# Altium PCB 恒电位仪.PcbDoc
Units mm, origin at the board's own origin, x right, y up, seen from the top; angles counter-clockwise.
Board outline 89.66 x 76.33 mm, 2 copper layers (Top Layer, Bottom Layer); 52 components, 39 nets, 177 pads, 10 vias.
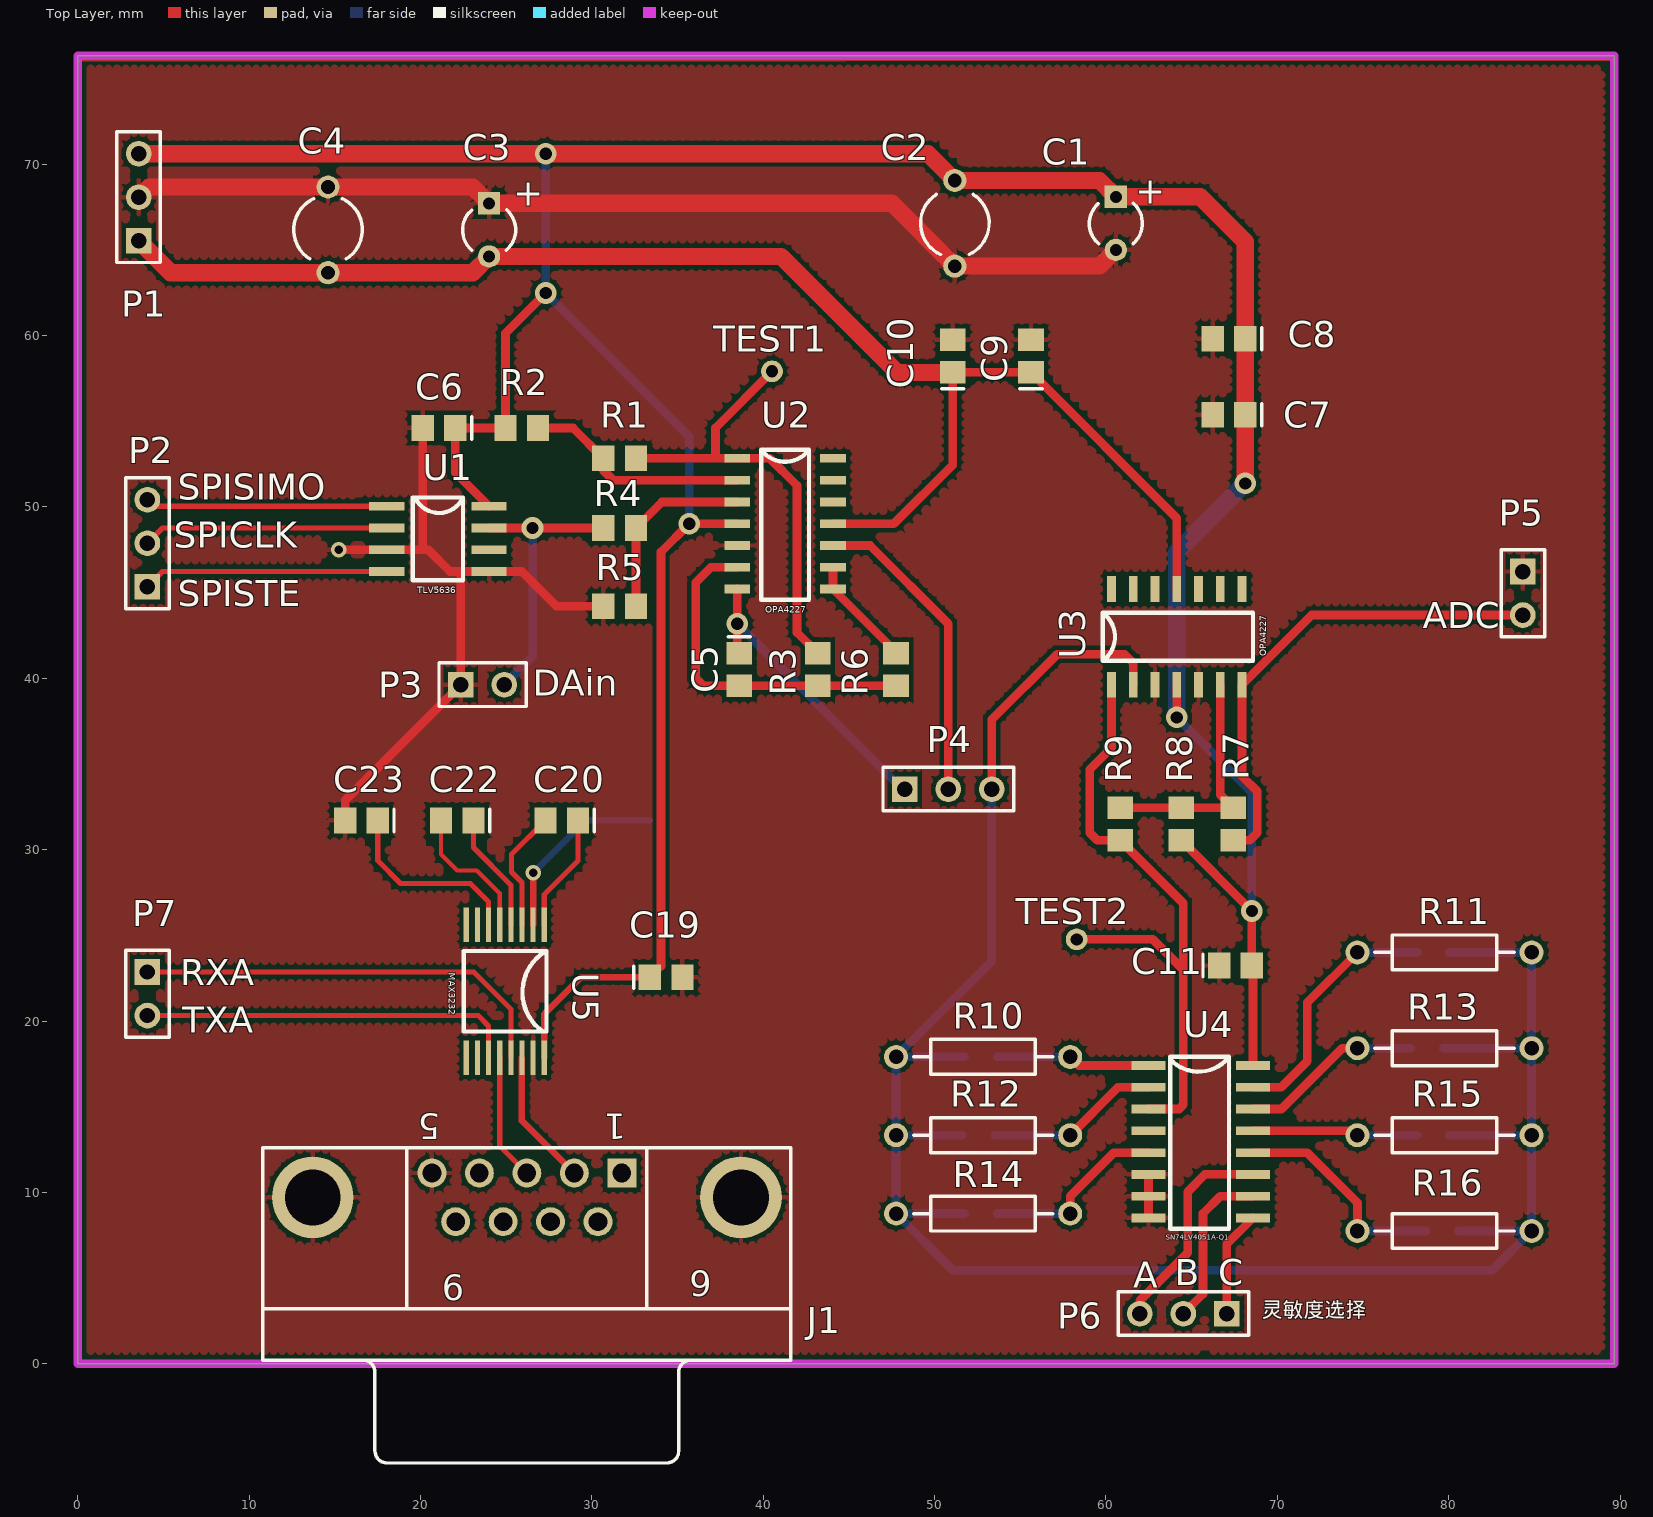
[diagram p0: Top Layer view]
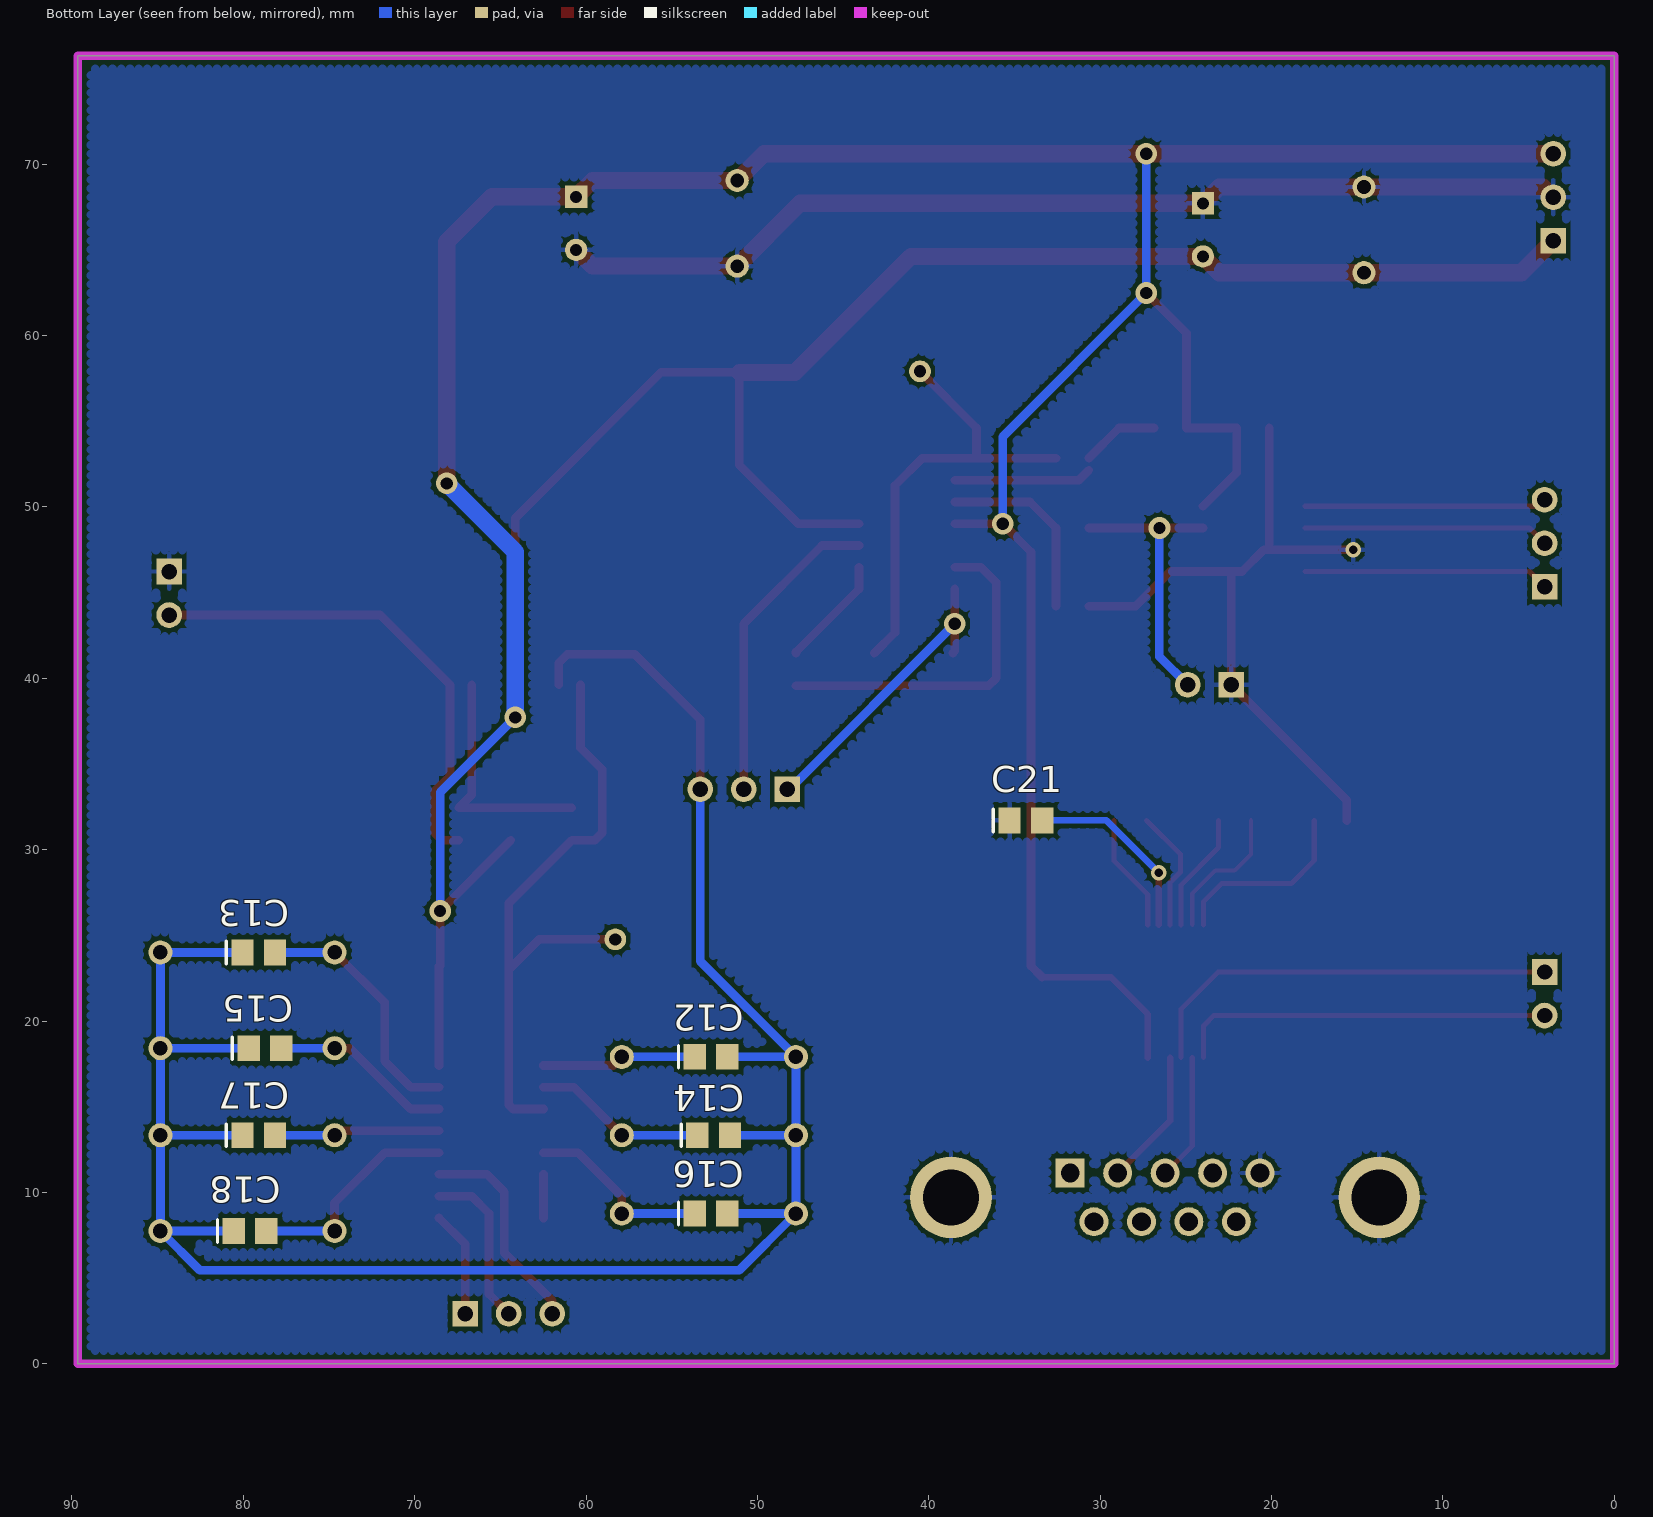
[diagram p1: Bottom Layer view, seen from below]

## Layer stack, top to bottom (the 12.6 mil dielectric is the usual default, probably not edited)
Top Layer: signal copper 0.0356
Dielectric: dielectric 0.32, FR-4, Dk 4.8
Bottom Layer: signal copper 0.0356

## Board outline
0,0 89.662,0 89.662,76.327 0,76.327

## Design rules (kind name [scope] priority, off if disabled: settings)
Clearance [All] p1: gap=0.254
ComponentClearance [All] p1 off: gap=0.254 collisioncheckmode=3 verticalgap=0.254
HoleSize [All] p1: absolutevalues=TRUE maxlimit=5.08 minlimit=0.025 maxpercent=80.000 minpercent=20.000
PolygonConnect [All] p1: connectstyle=Relief reliefconductorwidth=0.254 reliefentries=4 polygonreliefangle="90 Angle"
RoutingVias [All] p1: holewidth=0.511 width=1.27 viastyle="Through Hole" minholewidth=0.211 minwidth=0.7 maxholewidth=1.012 maxwidth=1.27
SolderMaskExpansion [All] p1: expansion=0.102
TestPointUsage [All] p1: valid=0 allowmultiple=FALSE
Testpoint [All] p1: side=15 testpointundercomponent=TRUE minsize=1.016 maxsize=2.54 preferedsize=1.524 minholesize=0 maxholesize=1.016 preferedholesize=0.813 testpointgrid=0.025 style=1023 order=0-112345678
Width GND [InNet('GND')] p1: maxlimit=1.2 minlimit=0.254 preferedwidth=0.508
Width -5V [InNet('-5V')] p2: maxlimit=1.2 minlimit=0.254 preferedwidth=0.508
Width +5V [InNet('+5V')] p3: maxlimit=1.262 minlimit=0.254 preferedwidth=0.508
Width [All] p4: maxlimit=0.762 minlimit=0.254 preferedwidth=0.254
17 further rules are at their usual default settings.

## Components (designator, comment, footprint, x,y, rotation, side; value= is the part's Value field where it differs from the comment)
C1 "Cap Pol1" R38 60.579,66.548 r0 top
C2 "Cap" CAPR5-4X5 51.181,66.548 r270 top
C3 "Cap Pol1" R38 24.003,66.167 r0 top
C4 "Cap" CAPR5-4X5 14.605,66.167 r90 top
C5 "Cap" C0805 38.608,40.513 r270 top
C6 "Cap" C0805 21.082,54.61 r180 top
C7 "Cap" C0805 67.183,55.372 r180 top
C8 "Cap" C0805 67.183,59.817 r180 top
C9 "Cap" C0805 55.626,58.801 r90 top
C10 "Cap" C0805 51.054,58.801 r90 top
C11 "Cap" C0805 67.564,23.241 r0 top
C12 "Cap" C0805 52.705,17.907 r180 bottom
C13 "Cap" C0805 79.099,24.003 r180 bottom
C14 "Cap" C0805 52.556,13.335 r180 bottom
C15 "Cap" C0805 78.74,18.415 r180 bottom
C16 "Cap" C0805 52.705,8.763 r180 bottom
C17 "Cap" C0805 79.099,13.335 r180 bottom
C18 "Cap" C0805 79.607,7.747 r180 bottom
C19 "Cap" C0805 34.335,22.561 r0 top
C20 "Cap" C0805 28.239,31.705 r180 top
C21 "Cap" C0805 34.335,31.705 r180 bottom
C22 "Cap" C0805 22.143,31.705 r180 top
C23 "Cap" C0805 16.555,31.705 r180 top
J1 "D Connector 9" DSUB1.385-2H9 26.207,0.209 r180 top
P1 "Header 3" HDR1X3 3.556,65.532 r90 top
P2 "Header 3" HDR1X3 4.064,45.339 r90 top
P3 "Header 2" HDR1X2 22.352,39.624 r0 top
P4 "Header 3" HDR1X3 48.26,33.528 r0 top
P5 "Header 2" HDR1X2 84.328,46.228 r270 top
P6 "Header 3" HDR1X3 67.056,2.921 r180 top
P7 "Header 2" HDR1X2 4.064,22.86 r270 top
R1 "Res2" 6-0805 31.623,52.832 r0 top
R2 "Res2" 6-0805 25.908,54.61 r0 top
R3 "Res2" 6-0805 43.18,40.513 r90 top
R4 "Res2" 6-0805 31.623,48.768 r0 top
R5 "Res2" 6-0805 31.623,44.196 r0 top
R6 "Res2" 6-0805 47.752,40.513 r270 top
R7 "Res2" 6-0805 67.437,31.496 r270 top
R8 "Res2" 6-0805 64.389,31.496 r90 top
R9 "Res2" 6-0805 60.833,31.496 r90 top
R10 "Res2" AXIAL-0.4 52.832,17.907 r180 top
R11 "Res2" AXIAL-0.4 79.756,24.003 r180 top
R12 "Res2" AXIAL-0.4 52.832,13.335 r180 top
R13 "Res2" AXIAL-0.4 79.756,18.415 r180 top
R14 "Res2" AXIAL-0.4 52.832,8.763 r180 top
R15 "Res2" AXIAL-0.4 79.756,13.335 r180 top
R16 "Res2" AXIAL-0.4 79.756,7.747 r180 top
U1 "TLV5636" TLV5636 18.034,50.038 r0 top
U2 "OPA4227" OPA4227 38.481,52.832 r0 top
U3 "OPA4227" OPA4227 60.325,39.624 r90 top
U4 "SN74LV4051A-Q1" SN74LV4051A-Q1 62.484,17.399 r0 top
U5 "MAX3232" MAX3232 27.223,25.609 r270 top

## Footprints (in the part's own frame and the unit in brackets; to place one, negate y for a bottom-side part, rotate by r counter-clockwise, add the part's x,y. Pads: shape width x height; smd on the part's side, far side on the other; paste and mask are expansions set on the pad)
6-0805 [mm] "Chip Resistor; Body 2.0 x 1.3 mm (LxW typ)"
  rect 1.3x1.5 smd: 1(-0.95,0) 2(0.95,0)
AXIAL-0.4 [mm] "Resistor; 2 Leads"
  round 1.4 hole 0.85: 1(-5.08,0) 2(5.08,0)
  silkscreen extent -4.06,-1.02 4.06,1.02
C0805 [mm] "Chip Capacitor; Body 2.0 x 1.2 mm (LxW typ)"
  rect 1.3x1.5 smd: 1(-0.95,0) 2(0.95,0)
  silkscreen extent -1.9,-0.65 -1.9,0.65
CAPR5-4X5 [mm] "Capacitor; 2 Leads"
  round 1.35 hole 0.8: 1(-2.5,0) 2(2.5,0)
  silkscreen extent -1.69,-2 1.82,2
DSUB1.385-2H9 [mm] "Connector; D Subminiature; 9 Position; Right Angle; Pitch 1.385 mm"
  rect 1.69x1.69 hole 1.09: 1(-5.54,-10.92)
  round 1.69 hole 1.09: 2(-2.77,-10.92) 3(0,-10.92) 4(2.77,-10.92) 5(5.54,-10.92) 6(-4.155,-8.08) 7(-1.385,-8.08) 8(1.385,-8.08) 9(4.155,-8.08)
  round 4.76 hole 3.26: 10(-12.495,-9.5) 11(12.495,-9.5)
  silkscreen extent -15.4,-12.4 15.4,6
HDR1X2 [mm] "Connector; Header; 2 Position"
  rect 1.5x1.5 hole 0.9: 1(0,0)
  round 1.5 hole 0.9: 2(2.54,0)
  silkscreen extent -1.27,-1.27 3.81,1.27
HDR1X3 [mm] "Connector; Header; 3 Position"
  rect 1.5x1.5 hole 0.9: 1(0,0)
  round 1.5 hole 0.9: 2(2.54,0) 3(5.08,0)
  silkscreen extent -1.27,-1.27 6.35,1.27
MAX3232 [mm]
  rect 2x0.3 smd: 1(0,0) 2(0,-0.65) 3(0,-1.3) 4(0,-1.95) 5(0,-2.6) 6(0,-3.25) 7(0,-3.9) 8(0,-4.55) 9(7.747,-4.55) 10(7.747,-3.9) 11(7.747,-3.25) 12(7.747,-2.6) 13(7.747,-1.95) 14(7.747,-1.3) 15(7.747,-0.65) 16(7.747,0)
  silkscreen extent 1.52,-4.7 6.22,0.13
OPA4227 [mm]
  rect 1.5x0.51 smd: 1(0,0) 2(0,-1.27) 3(0,-2.54) 4(0,-3.81) 5(0,-5.08) 6(0,-6.35) 7(0,-7.62) 8(5.588,-7.62) 9(5.588,-6.35) 10(5.588,-5.08) 11(5.588,-3.81) 12(5.588,-2.54) 13(5.588,-1.27) 14(5.588,0)
  silkscreen extent 1.4,-8.25 4.19,0.51
R38 [mm] "Crystal, Thru-Hole; 2 Leads; Body 3.1 x 8.2 mm (Dia.xH)"
  rect 1.3x1.3 hole 0.7: 1(0,1.55)
  round 1.3 hole 0.7: 2(0,-1.55)
  silkscreen extent -1.55,-1.19 1.55,1.17
SN74LV4051A-Q1 [mm]
  rect 2x0.51 smd: 1(0,0) 2(0,-1.27) 3(0,-2.54) 4(0,-3.81) 5(0,-5.08) 6(0,-6.35) 7(0,-7.62) 8(0,-8.89) 9(6.096,-8.89) 10(6.096,-7.62) 11(6.096,-6.35) 12(6.096,-5.08) 13(6.096,-3.81) 14(6.096,-2.54) 15(6.096,-1.27) 16(6.096,0)
  silkscreen extent 1.26,-9.53 4.7,0.51
TLV5636 [mm]
  rect 2.05x0.51 smd: 1(0,0) 2(0,-1.27) 3(0,-2.54) 4(0,-3.81) 5(5.969,-3.81) 6(5.969,-2.54) 7(5.969,-1.27) 8(5.969,0)
  silkscreen extent 1.52,-4.32 4.44,0.51

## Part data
C1 C3: "Polarized Capacitor (Radial)"
C2 C4 C5 C6 C7 C8 C9 C10 C11 C12 C13 C14 C15 C16 C17 C18 C19 C20 C21 C22 C23: "Capacitor"
J1: "Receptacle Assembly, 9 Position, Right Angle"
P1 P2 P4 P6: "Header, 3-Pin"
P3 P5 P7: "Header, 2-Pin"
R1 R2 R3 R4 R5 R6 R7 R8 R9 R10 R11 R12 R13 R14 R15 R16: "Resistor"

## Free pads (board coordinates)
  round 1.27 hole 0.711: 1(40.513,57.912) 2(58.293,24.765)

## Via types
v1: diameter 1.27, hole 0.711, Top Layer to Bottom Layer, 8 vias
v2: diameter 0.9, hole 0.5, Top Layer to Bottom Layer, 2 vias

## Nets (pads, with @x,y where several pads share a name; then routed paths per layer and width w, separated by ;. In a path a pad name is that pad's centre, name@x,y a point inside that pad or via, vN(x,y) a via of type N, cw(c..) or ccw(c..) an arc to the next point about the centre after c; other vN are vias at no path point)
+5: 
+5V: C1.1 C2.1 C6.1 C7.1 C8.1 C11.2 C19.1 P1.3 R2.1 R8.1 U1.8 U2.4 U3.4 U4.16 U5.16 | length 208.2
  Top Layer w0.381: U5.16 27.223,20.402 29.382,22.561 C19.1
  Top Layer w0.508: U1.8 22.032,52.009 C6.1 R2.1 24.958,60.137 v1(27.305,62.484) ; C19.1 34.036,23.212 34.036,47.371 v1(35.687,49.022) U2.4 ; 39.116,70.485 39.116,70.612 ; v1(64.135,37.719) U3.4 ; R8.1 v1(68.514,26.421) C11.2 68.58,23.175 U4.16
  Top Layer w1: P1.3 49.617,70.612 C2.1 59.629,69.048 C1.1 65.506,68.098 68.133,65.471 v1(68.133,51.374)
  Bottom Layer w0.508: v1(27.305,70.612) v1(27.305,62.484) 35.687,54.102 v1(35.687,49.022) ; v1(64.135,37.719) 68.514,33.34 v1(68.514,26.421)
  Bottom Layer w1: v1(64.135,37.719) 64.135,47.376 v1(68.133,51.374)
-5V: C3.2 C4.1 C9.1 C10.1 P1.1 U2.11 U3.11 | length 86
  Top Layer w0.508: U2.11 47.625,49.022 51.054,52.451 C10.1 C9.1 64.135,49.342 U3.11
  Top Layer w1: P1.1 5.421,63.667 23.053,63.667 C3.2 41.047,64.617 47.813,57.851 C10.1
A: P6.3 U4.11 | length 12.5
  Top Layer w0.508: P6.3 61.976,3.683 64.77,6.477 64.77,10.033 65.786,11.049 U4.11
B: P6.2 U4.10 | length 9.7
  Top Layer w0.508: P6.2 65.659,4.064 65.659,8.763 66.675,9.779 U4.10
C: P6.1 U4.9 | length 6.2
  Top Layer w0.508: P6.1 67.056,6.985 U4.9
GND: C1.2 C2.2 C3.1 C4.2 C6.2 C7.2 C8.2 C9.2 C10.2 C11.1 C19.2 C21.1 C23.2 J1.5 J1.10 J1.11 P1.2 P3.1 P5.1 R5.1 U1.3 U1.5 U2.5 U3.3 U3.5 U4.6 U4.7 U4.8 U5.15 | length 103.4
  Top Layer w0.508: v2(15.24,47.498) 20.447,47.498 21.717,46.228 25.908,46.228 27.94,44.196 R5.1 ; C23.2 15.605,32.877 P3.1 22.352,46.228 ; 20.066,47.498 20.132,47.564 C6.2 ; U4.8 U4.6
  Top Layer w1: P1.2 4.151,68.667 23.053,68.667 C3.1 47.512,67.717 C2.2 59.629,64.048 C1.2
NetC5_1: C5.1 P4.1 U2.7 | length 17.6
  Top Layer w0.508: U2.7 38.481,41.59 C5.1
  Bottom Layer w0.508: v1(38.481,43.18) 48.133,33.528 P4.1
NetC5_2: C5.2 R3.1 R6.2 U2.6 | length 20.2
  Top Layer w0.508: U2.6 36.957,46.482 36.068,45.593 36.068,40.005 36.51,39.563 C5.2 R3.1 R6.2
NetC12_1: C12.1 R10.1 U4.1 | length 9
  Top Layer w0.508: R10.1 58.42,17.399 U4.1
  Bottom Layer w0.508: C12.1 R10.1
NetC12_2: C12.2 C13.1 C14.2 C15.1 C16.2 C17.1 C18.1 P4.3 R10.2 R11.1 R12.2 R13.1 R14.2 R15.1 R16.1 U3.2 | length 129
  Top Layer w0.508: P4.3 53.34,37.592 57.15,41.402 61.087,41.402 61.595,40.894 U3.2
  Bottom Layer w0.508: R12.2 C14.2 ; C16.2 R14.2 ; C12.2 R10.2 ; P4.3 53.34,23.495 R10.2 ; C15.1 R13.1 ; C17.1 R15.1 ; C13.1 R11.1 R13.1 ; C18.1 R16.1 ; R14.2 R10.2 ; R14.2 51.054,5.461 82.55,5.461 R16.1 ; R16.1 R15.1 ; R15.1 R13.1
NetC13_2: C13.2 R11.2 U4.15 | length 14.8
  Top Layer w0.508: U4.15 70.231,16.129 71.755,17.653 71.755,21.082 R11.2
  Bottom Layer w0.508: R11.2 C13.2
NetC14_1: C14.1 R12.1 U4.2 | length 10.1
  Top Layer w0.508: R12.1 60.706,16.129 U4.2
  Bottom Layer w0.508: C14.1 R12.1
NetC15_2: C15.2 R13.2 U4.14 | length 10.7
  Top Layer w0.508: U4.14 70.231,14.859 73.787,18.415 R13.2
  Bottom Layer w0.508: R13.2 C15.2
NetC16_1: C16.1 R14.1 U4.5 | length 10.9
  Top Layer w0.508: R14.1 57.912,9.779 60.452,12.319 U4.5
  Bottom Layer w0.508: C16.1 R14.1
NetC17_2: C17.2 R15.2 U4.13 | length 9.7
  Top Layer w0.508: U4.13 74.422,13.589 R15.2
  Bottom Layer w0.508: R15.2 C17.2
NetC18_2: C18.2 R16.2 U4.12 | length 12.9
  Top Layer w0.508: U4.12 71.755,12.319 74.676,9.398 R16.2
  Bottom Layer w0.508: R16.2 C18.2
NetC20_1: C20.1 U5.1 | length 6.9
  Top Layer w0.3: U5.1 27.223,27.387 29.189,29.353 C20.1
NetC20_2: C20.2 U5.3 | length 7.2
  Top Layer w0.3: U5.3 25.923,28.088 25.318,28.693 25.318,29.734 C20.2
NetC21_2: C21.2 U5.2 | length 11.1
  Top Layer w0.381: U5.2 v2(26.573,28.642)
  Bottom Layer w0.381: v2(26.573,28.642) 29.636,31.705 C21.2
NetC22_1: C22.1 U5.4 | length 7
  Top Layer w0.3: C22.1 23.093,30.12 25.273,27.94 U5.4
NetC22_2: C22.2 U5.5 | length 8.2
  Top Layer w0.254: C22.2 21.193,29.734 22.143,28.784 23.286,28.784 24.623,27.447 U5.5
NetC23_1: C23.1 U5.6 | length 11.2
  Top Layer w0.3: C23.1 17.505,29.358 18.841,28.022 22.905,28.022 23.973,26.954 U5.6
NetJ1_2: J1.2 U5.14 | length 8
  Top Layer w0.381: U5.14 25.923,14.183 J1.2
NetP2_1: P2.1 U1.4 | length 14.3
  Top Layer w0.3: P2.1 4.953,46.228 U1.4
NetP2_2: P2.2 U1.2 | length 14.3
  Top Layer w0.3: P2.2 4.953,48.768 U1.2
NetP2_3: P2.3 U1.1 | length 14.1
  Top Layer w0.3: P2.3 4.445,50.038 U1.1
NetP3_2: P3.2 R4.1 U1.7 | length 16.5
  Top Layer w0.508: U1.7 R4.1
  Bottom Layer w0.508: P3.2 26.543,41.275 v1(26.543,48.768)
NetP4_2: P4.2 U2.10 | length 18.3
  Top Layer w0.508: U2.10 46.228,47.752 50.8,43.18 P4.2
NetP5_2: P5.2 R7.2 U3.7 | length 28.7
  Top Layer w0.508: R7.2 68.392,30.546 68.834,30.988 68.834,33.401 67.945,34.29 U3.7 72.009,43.688 P5.2
NetP7_1: P7.1 U5.13 | length 24.9
  Top Layer w0.3: P7.1 23.114,22.86 25.273,20.701 U5.13
NetP7_2: P7.2 U5.11 | length 22
  Top Layer w0.3: P7.2 23.368,20.32 23.973,19.715 U5.11
NetR1_1: R1.1 R2.2 U2.2 | length 12.6
  Top Layer w0.508: R2.2 28.895,54.61 R1.1 ; R1.1@30.673,52.131 31.242,51.562 U2.2
NetR1_2: pad.1 R1.2 R3.2 U2.1 | length 26.8
  Top Layer w0.508: R1.2 40.386,52.832 41.971,51.247 41.971,42.672 R3.2 ; 37.084,52.832 37.211,52.959 37.211,54.61 pad.1
NetR4_2: R4.2 R5.2 U2.3 | length 11.1
  Top Layer w0.508: R5.2 R4.2 34.097,50.292 U2.3
NetR6_1: R6.1 U2.8 U2.9 | length 6.5
  Top Layer w0.508: U2.9 U2.8 47.752,41.529 R6.1
NetR7_1: R7.1 R8.2 R9.2 U3.6 | length 14.1
  Top Layer w0.508: R9.2 R7.1 66.675,33.208 U3.6
NetR9_1: pad.2 R9.1 U3.1 U4.3 | length 37.2
  Top Layer w0.508: pad.2 62.738,24.765 64.516,22.987 ; U3.1 60.325,35.941 59.055,34.671 59.055,30.988 59.497,30.546 R9.1 64.516,26.863 64.516,15.113 64.262,14.859 U4.3
ROUT1: J1.3 U5.12 | length 7.4
  Top Layer w0.3: U5.12 24.623,12.713 J1.3
pads on no net: J1.1 J1.4 J1.6 J1.7 J1.8 J1.9 U1.6 U2.12 U2.13 U2.14 U3.8 U3.9 U3.10 U3.12 U3.13 U3.14 U4.4 U5.7 U5.8 U5.9 U5.10

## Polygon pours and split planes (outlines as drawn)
GND on Top Layer "TopLayer-No Net" (hatched 90Degree grid 0.508 track 0.508, remove dead copper): -7.366,82.804 107.061,82.804 107.442,82.423 108.458,81.407 108.458,-19.304 -4.572,-19.304 -14.478,-9.398 -7.112,-2.032 -7.112,83.058
GND on Top Layer "TopLayer-No Net" (hatched 90Degree grid 0.508 track 0.508, remove dead copper): 0,75.946 0.127,76.073 89.662,76.073
GND on Bottom Layer "TopLayer-No Net" (hatched 90Degree grid 0.508 track 0.508, remove dead copper): -11.049,83.82 -8.763,86.106 105.791,86.106 105.791,-23.622 103.632,-25.781 103.124,-25.273 -16.383,-25.273 -16.383,78.486 -11.049,83.82

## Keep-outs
Keep-Out Layer:
  the board outline again, w0.508

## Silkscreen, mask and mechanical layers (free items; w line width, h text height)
Top Overlay:
  text "+" at 61.722,67.691 h1.52
  text "+" at 25.4,67.564 h1.52
  text "TEST1" at 37.084,59.055 h1.52
  text "SPISIMO" at 5.842,50.419 h1.52
  text "SPICLK" at 5.588,47.625 h1.52
  text "SPISTE" at 5.842,44.196 h1.52
  text "ADC" at 78.486,42.926 h1.52
  text "DAin" at 26.543,38.989 h1.52
  text "TEST2" at 54.737,25.654 h1.52
  text "RXA" at 5.969,22.098 h1.52
  text "TXA" at 6.096,19.304 h1.52
  text "B" at 64.008,4.572 h1.52
  text "C" at 66.548,4.572 h1.52
  text "A" at 61.595,4.445 h1.52
  text "灵敏度选择" at 69.088,2.413 h1.52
